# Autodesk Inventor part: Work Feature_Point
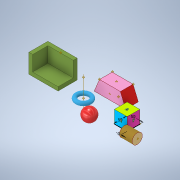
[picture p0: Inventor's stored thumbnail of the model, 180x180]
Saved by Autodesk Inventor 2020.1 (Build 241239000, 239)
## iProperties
Created: 2018-06
Part Number: Work Feature_Point
Material: Generic
Document SubType Name: Modeling
Designer: Power User
Density: 1 g/cm^3
Appearance: Light Red
Author: Power User
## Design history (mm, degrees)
sketch "Sketch1"
  geometry: L1 (0, 0)-(50, 0); L2 (50, 0)-(50, -50); L3 (50, -50)-(0, -50); L4 (0, -50)-(0, 0); 1 further point
  constraints: 8 end point, 2 parallel, 1 coincident, 1 horizontal, 1 perpendicular
  dimensions: "d0" = 50 distance of L1.end L2.end; "d1" = 50 distance of L2.end L3.end; "d53" = 0 distance from line of point (0, 0) L4
extrude "Extrusion1" new body sketch "Sketch1" distance "d2" = 50; taper "d3" = 0 deg
workplane "Work Plane1"
sketch "Sketch2"
  geometry: L1 (0, 50)-(50, 50) reference; L2 (50, 0)-(50, 50) reference; C1 r 20 at (-30, 25); 3 further points
  constraints: 2 midpoint, 1 centre point, 1 horizontal alignment
  dimensions: "d5" = 40 diameter of C1; "d54" = 30 horizontal distance of C1.centre point (0, 0)
extrude "Extrusion2" new body sketch "Sketch2" distance "d6" = 50; taper "d7" = 0 deg
sketch "Sketch3"
  geometry: L1 (-172.16, 49.98)-(-172.16, 11.482); C1 r 7.5 at (-197.16, 26.587); 1 further point
  constraints: 2 end point, 1 centre point, 1 vertical
  dimensions: "d8" = 15 diameter of C1; "d9" = 50 diameter of C1.centre L1
revolve "Revolution1" sketch "Sketch3" stored, may be unused: angle "d10" = 90 deg
workplane "Work Plane2"
sketch "Sketch4"
  geometry: L1 (-98.807, 58.325)-(-98.807, 8.325); A1 r 25 centre (-98.807, 33.325) between (-98.807, 58.325) and (-98.807, 8.325); 1 further point
  constraints: 2 end point, 2 point on circle, 1 centre point, 1 vertical
  dimensions: "d12" = 50 diameter of A1
revolve "Revolution2" sketch "Sketch4" stored, may be unused: angle "d13" = 90 deg
workplane "Work Plane3"
sketch "Sketch5"
  geometry: L1 (-192.037, 9.98)-(-171.326, 59.98); L2 (-171.326, 59.98)-(-89.041, 59.98); L3 (-89.041, 59.98)-(-68.33, 9.98); L4 (-68.33, 9.98)-(-192.037, 9.98); L5 (-130.184, 59.98)-(-130.184, 9.98); 1 further point
  constraints: 10 end point, 2 midpoint, 1 horizontal, 1 parallel, 1 perpendicular, 1 other
  dimensions: "d15" = 50 distance between parallel lines of L4 L2; "d16" = 45 deg angle of L3 L1
extrude "Extrusion3" new body sketch "Sketch5" stored distance "d17" = 50; taper "d18" = 0 deg
sketch "Sketch6"
  geometry: L1 (15, 35)-(35, 35); L2 (35, 35)-(35, 15); L3 (35, 15)-(15, 15); L4 (15, 15)-(15, 35); L5 (0, 50)-(50, 50) reference; L6 (0, 0)-(0, 50) reference; 5 further points
  constraints: 4 midpoint, 1 horizontal alignment, 1 vertical alignment, 2 other
  dimensions: "d19" = 20 distance of L1.start L1.end; "d20" = 20 distance of L1.end L2.end
emboss "Emboss1" sketch "Sketch6" dims "d0" = 50, "d1" = 50, "d21" = 0.2, "d22" = 0, "d53" = 0
sketch "Sketch7"
  geometry: L1 (-35, 35)-(-15, 35); L2 (-15, 35)-(-15, 15); L3 (-15, 15)-(-35, 15); L4 (-35, 15)-(-35, 35); L5 (0, 50)-(-50, 50) reference; L6 (-50, 50)-(-50, 0) reference; 5 further points
  constraints: 4 midpoint, 1 horizontal alignment, 1 vertical alignment, 2 other
  dimensions: "d23" = 20 distance of L1.start L1.end; "d24" = 20 distance of L3.end L1.start
emboss "Emboss2" sketch "Sketch7" dims "d0" = 50, "d1" = 50, "d25" = 0.2, "d26" = 0, "d53" = 0
sketch "Sketch8"
  geometry: L1 (15, 35)-(35, 35); L2 (35, 35)-(35, 15); L3 (35, 15)-(15, 15); L4 (15, 15)-(15, 35); L5 (0, 0)-(0, 50) reference; L6 (0, 50)-(50, 50) reference; 4 further points
  constraints: 4 midpoint, 1 horizontal alignment, 1 vertical alignment, 2 other
  dimensions: "d27" = 20 distance of L1.start L1.end; "d28" = 20 distance of L3.end L1.start
emboss "Emboss3" sketch "Sketch8" dims "d0" = 50, "d1" = 50, "d29" = 0.2, "d30" = 0, "d53" = 0
sketch "Sketch9"
  geometry: L1 (-11.219, -35.018)-(-35.694, -35.018); L2 (-35.694, -35.018)-(-35.694, -14.982); L3 (-35.694, -14.982)-(-11.219, -14.982); L4 (-11.219, -14.982)-(-11.219, -35.018); L5 (0, -50)-(0, 0) reference; 4 further points
  constraints: 3 midpoint, 1 horizontal alignment, 1 vertical alignment, 2 other
emboss "Emboss4" sketch "Sketch9" dims "d0" = 50, "d1" = 50, "d31" = 0.2, "d32" = 0, "d53" = 0
sketch "Sketch10"
  geometry: L1 (15, 35)-(35, 35); L2 (35, 35)-(35, 15); L3 (35, 15)-(15, 15); L4 (15, 15)-(15, 35); L5 (0, 50)-(50, 50) reference; L6 (0, 0)-(0, 50) reference; 5 further points
  constraints: 4 midpoint, 1 horizontal alignment, 1 vertical alignment, 2 other
  dimensions: "d33" = 20 distance of L1.start L1.end; "d34" = 20 distance of L3.end L1.start
emboss "Emboss5" sketch "Sketch10" dims "d0" = 50, "d1" = 50, "d35" = 0.2, "d36" = 0, "d53" = 0
sketch "Sketch11"
  geometry: L1 (15, 35)-(35, 35); L2 (35, 35)-(35, 15); L3 (35, 15)-(15, 15); L4 (15, 15)-(15, 35); L5 (0, 0)-(0, 50) reference; L6 (0, 50)-(50, 50) reference; 4 further points
  constraints: 4 midpoint, 1 horizontal alignment, 1 vertical alignment, 2 other
  dimensions: "d37" = 20 distance of L1.start L1.end; "d38" = 20 distance of L1.end L2.end
emboss "Emboss6" sketch "Sketch11" dims "d0" = 50, "d1" = 50, "d39" = 0.2, "d40" = 0, "d53" = 0
sketch "Sketch12"
  geometry: L1 (118.439, 97.246)-(43.439, 97.246); L2 (43.439, 97.246)-(43.439, 172.246); L3 (43.439, 172.246)-(58.439, 172.246); L4 (58.439, 172.246)-(58.439, 112.246); L5 (58.439, 112.246)-(118.439, 112.246); L6 (118.439, 112.246)-(118.439, 97.246); 1 further point
  constraints: 12 end point, 4 perpendicular, 1 horizontal, 1 vertical
  dimensions: "d41" = 75 distance of L1.start L1.end; "d42" = 75 distance of L1.end L2.end (= d41); "d43" = 15 distance of L5.end L1.start; "d44" = 15 distance of L2.end L3.end (= d43)
extrude "Extrusion4" new body sketch "Sketch12" stored distance "d45" = 100; taper "d46" = 0 deg
sketch "Sketch13"
  geometry: L1 (97.246, 118.439)-(97.246, 43.439) reference; L2 (97.246, 43.439)-(172.246, 43.439) reference; L3 (172.246, 43.439)-(97.246, 43.439) reference; L4 (172.246, 118.439)-(97.246, 118.439); L5 (97.246, 118.439)-(97.246, 43.439); L6 (97.246, 43.439)-(172.246, 43.439); L7 (172.246, 43.439)-(172.246, 118.439); L8 (172.246, 118.439)-(97.246, 43.439); L9 (97.246, 118.439)-(172.246, 43.439); 2 further points
  constraints: 12 end point, 2 equal length, 2 midpoint, 2 parallel, 1 horizontal, 1 perpendicular
extrude "Extrusion5" join sketch "Sketch13" distance "d47" = 15; taper "d48" = 0 deg
feature "Move Body1"
workpoint "Work Point4"
workpoint "Work Point5"
workpoint "Work Point6"
workpoint "Work Point7"
workpoint "Work Point8"
workpoint "Work Point9"
workpoint "Work Point10"
workpoint "Work Point11"
  workaxis "Work Axis1"
workpoint "Work Point12"
workpoint "Work Point13"
workpoint "Work Point14"
workpoint "Work Point15"
workpoint "Work Point16"
node "Cube"
node "Cylinder"
node "Ring"
node "Sphere"
node "Trapezoid"
node "Solid"
other parameters: "d14" = -87.5
